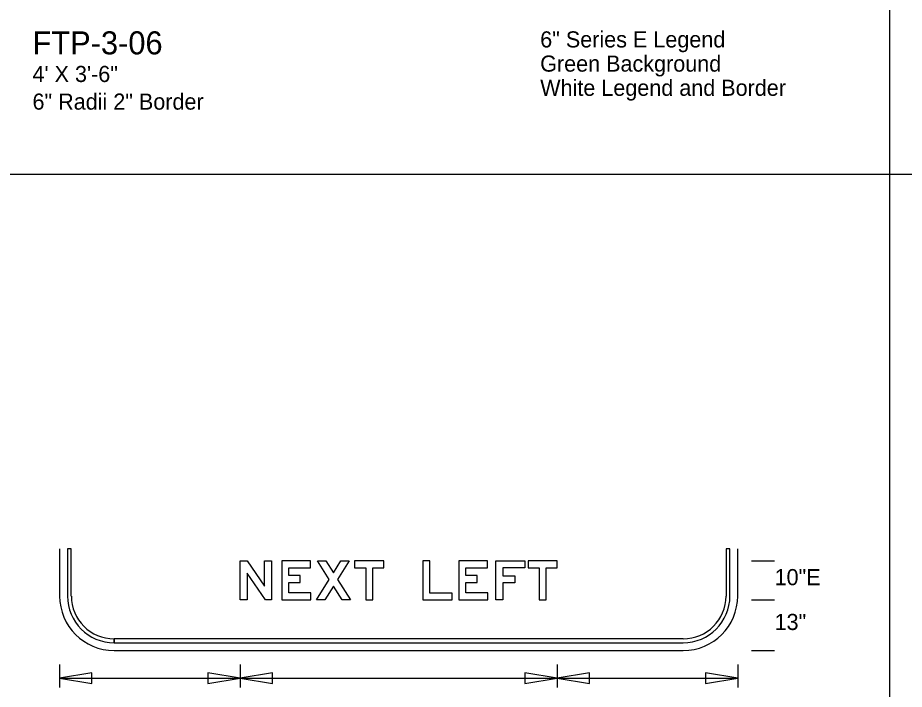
# Model space of a CAD drawing. Extents: x 0 to 770, y 0 to 495.
# Drawn here: x 388.5 to 580.9, y 218.2 to 364 of the extents above; entities that cross this region are included whole.
import ezdxf

# ---------------------------------------------------------------- set-up
doc = ezdxf.new("R2010")
doc.units = 0
for name, color, linetype in [('Dimension', 7, 'Continuous'), ('GSBWFill', 7, 'Continuous'), ('GSColorFill', 7, 'Continuous'), ('GSDims', 7, 'Continuous'), ('GSOutline', 7, 'Continuous'), ('SheetLines_dp', 7, 'Continuous'), ('TextStructures', 7, 'Continuous')]:
    doc.layers.add(name, color=color, linetype=linetype)

msp = doc.modelspace()

# ---------------------------------------------------------------- linework, layer by layer
at = {"layer": 'Dimension'}
for points in [[(397.61, 220.64), (404.63, 219.46), (404.63, 221.83)], [(436.78, 220.64), (429.76, 221.83), (429.76, 219.46)], [(436.78, 220.64), (443.79, 219.46), (443.79, 221.83)], [(505.63, 220.64), (498.61, 221.83), (498.61, 219.46)], [(505.63, 220.64), (512.65, 219.46), (512.65, 221.83)], [(544.79, 220.64), (537.78, 221.83), (537.78, 219.46)]]:
    msp.add_lwpolyline(points, close=True, dxfattribs=at)
at = {"layer": 'GSBWFill'}
for p, q in [((397.61, 248.73), (397.61, 238.48)), ((399.31, 248.73), (399.31, 238.48)), ((400.15, 238.48), (400.15, 248.73)), ((542.26, 248.73), (542.26, 238.48)), ((543.1, 238.48), (543.1, 248.73)), ((544.79, 238.48), (544.79, 248.73)), ((409.46, 228.33), (409.46, 229.18)), ((532.95, 229.18), (409.47, 229.18)), ((409.47, 229.18), (409.47, 228.33)), ((409.47, 228.33), (532.95, 228.33)), ((409.46, 226.64), (532.95, 226.64))]:
    msp.add_line(p, q, dxfattribs=at)
for points in [[(400.15, 248.73), (399.31, 248.73)], [(543.1, 248.73), (542.26, 248.73)]]:
    msp.add_lwpolyline(points, dxfattribs=at)
for points in [[(443.63, 246.09), (443.63, 237.64), (442.32, 237.64), (438.3, 243.43), (438.3, 237.64), (436.78, 237.64), (436.78, 246.09), (438.31, 246.09), (442.11, 240.61), (442.11, 246.09)], [(452.17, 239.16), (447.35, 239.16), (447.35, 241.43), (449.85, 241.43), (449.85, 242.96), (447.35, 242.96), (447.35, 244.57), (452.05, 244.57), (452.05, 246.09), (445.83, 246.09), (445.83, 237.64), (452.17, 237.64)], [(458.92, 237.64), (457.04, 240.63), (455.15, 237.64), (453.36, 237.64), (456.14, 242.07), (453.61, 246.09), (455.41, 246.09), (457.04, 243.5), (458.66, 246.09), (460.46, 246.09), (457.93, 242.07), (460.72, 237.64)], [(461.65, 244.57), (464.06, 244.57), (464.06, 237.64), (465.58, 237.64), (465.58, 244.57), (467.99, 244.57), (467.99, 246.09), (461.65, 246.09)], [(482.79, 237.64), (482.79, 239.12), (477.97, 239.12), (477.97, 246.09), (476.45, 246.09), (476.45, 237.64)], [(490.57, 239.16), (485.75, 239.16), (485.75, 241.43), (488.25, 241.43), (488.25, 242.96), (485.75, 242.96), (485.75, 244.57), (490.45, 244.57), (490.45, 246.09), (484.23, 246.09), (484.23, 237.64), (490.57, 237.64)], [(493.79, 241.36), (493.79, 237.64), (492.27, 237.64), (492.27, 246.09), (498.61, 246.09), (498.61, 244.57), (493.79, 244.57), (493.79, 242.88), (496.45, 242.88), (496.45, 241.36)], [(499.29, 244.57), (501.7, 244.57), (501.7, 237.64), (503.22, 237.64), (503.22, 244.57), (505.63, 244.57), (505.63, 246.09), (499.29, 246.09)]]:
    msp.add_lwpolyline(points, close=True, dxfattribs=at)
for centre, radius, start, end in [((409.46, 238.48), 11.84, 180, 270), ((409.46, 238.48), 10.15, 180, 270), ((409.46, 238.48), 9.3, 180, 270), ((532.95, 238.48), 9.3, 270, 0), ((532.95, 238.48), 10.15, 270, 0), ((532.95, 238.48), 11.84, 270, 0)]:
    msp.add_arc(centre, radius, start, end, dxfattribs=at)
at = {"layer": 'GSColorFill'}
for points in [[(443.63, 246.09), (443.63, 237.64), (442.32, 237.64), (438.3, 243.43), (438.3, 237.64), (436.78, 237.64), (436.78, 246.09), (438.31, 246.09), (442.11, 240.61), (442.11, 246.09)], [(452.17, 239.16), (447.35, 239.16), (447.35, 241.43), (449.85, 241.43), (449.85, 242.96), (447.35, 242.96), (447.35, 244.57), (452.05, 244.57), (452.05, 246.09), (445.83, 246.09), (445.83, 237.64), (452.17, 237.64)], [(458.92, 237.64), (457.04, 240.63), (455.15, 237.64), (453.36, 237.64), (456.14, 242.07), (453.61, 246.09), (455.41, 246.09), (457.04, 243.5), (458.66, 246.09), (460.46, 246.09), (457.93, 242.07), (460.72, 237.64)], [(461.65, 244.57), (464.06, 244.57), (464.06, 237.64), (465.58, 237.64), (465.58, 244.57), (467.99, 244.57), (467.99, 246.09), (461.65, 246.09)], [(482.79, 237.64), (482.79, 239.12), (477.97, 239.12), (477.97, 246.09), (476.45, 246.09), (476.45, 237.64)], [(490.57, 239.16), (485.75, 239.16), (485.75, 241.43), (488.25, 241.43), (488.25, 242.96), (485.75, 242.96), (485.75, 244.57), (490.45, 244.57), (490.45, 246.09), (484.23, 246.09), (484.23, 237.64), (490.57, 237.64)], [(493.79, 241.36), (493.79, 237.64), (492.27, 237.64), (492.27, 246.09), (498.61, 246.09), (498.61, 244.57), (493.79, 244.57), (493.79, 242.88), (496.45, 242.88), (496.45, 241.36)], [(499.29, 244.57), (501.7, 244.57), (501.7, 237.64), (503.22, 237.64), (503.22, 244.57), (505.63, 244.57), (505.63, 246.09), (499.29, 246.09)]]:
    msp.add_lwpolyline(points, close=True, dxfattribs=at)
at = {"layer": 'GSDims'}
for p, q in [((547.79, 246.09), (552.79, 246.09)), ((547.79, 246.09), (552.79, 246.09)), ((547.79, 237.64), (552.79, 237.64)), ((547.79, 237.64), (552.79, 237.64)), ((547.79, 226.64), (552.79, 226.64)), ((397.61, 223.64), (397.61, 218.65)), ((436.78, 223.64), (436.78, 218.65)), ((436.78, 223.64), (436.78, 218.65)), ((505.63, 223.64), (505.63, 218.65)), ((505.63, 223.64), (505.63, 218.65)), ((544.79, 223.64), (544.79, 218.65)), ((397.61, 220.64), (436.78, 220.64)), ((436.78, 220.64), (505.63, 220.64)), ((505.63, 220.64), (544.79, 220.64))]:
    msp.add_line(p, q, dxfattribs=at)
at = {"layer": 'GSOutline'}
for points in [[(443.63, 246.09), (443.63, 237.64), (442.32, 237.64), (438.3, 243.43), (438.3, 237.64), (436.78, 237.64), (436.78, 246.09), (438.31, 246.09), (442.11, 240.61), (442.11, 246.09)], [(452.17, 239.16), (447.35, 239.16), (447.35, 241.43), (449.85, 241.43), (449.85, 242.96), (447.35, 242.96), (447.35, 244.57), (452.05, 244.57), (452.05, 246.09), (445.83, 246.09), (445.83, 237.64), (452.17, 237.64)], [(458.92, 237.64), (457.04, 240.63), (455.15, 237.64), (453.36, 237.64), (456.14, 242.07), (453.61, 246.09), (455.41, 246.09), (457.04, 243.5), (458.66, 246.09), (460.46, 246.09), (457.93, 242.07), (460.72, 237.64)], [(461.65, 244.57), (464.06, 244.57), (464.06, 237.64), (465.58, 237.64), (465.58, 244.57), (467.99, 244.57), (467.99, 246.09), (461.65, 246.09)], [(482.79, 237.64), (482.79, 239.12), (477.97, 239.12), (477.97, 246.09), (476.45, 246.09), (476.45, 237.64)], [(490.57, 239.16), (485.75, 239.16), (485.75, 241.43), (488.25, 241.43), (488.25, 242.96), (485.75, 242.96), (485.75, 244.57), (490.45, 244.57), (490.45, 246.09), (484.23, 246.09), (484.23, 237.64), (490.57, 237.64)], [(493.79, 241.36), (493.79, 237.64), (492.27, 237.64), (492.27, 246.09), (498.61, 246.09), (498.61, 244.57), (493.79, 244.57), (493.79, 242.88), (496.45, 242.88), (496.45, 241.36)], [(499.29, 244.57), (501.7, 244.57), (501.7, 237.64), (503.22, 237.64), (503.22, 244.57), (505.63, 244.57), (505.63, 246.09), (499.29, 246.09)]]:
    msp.add_lwpolyline(points, close=True, dxfattribs=at)
at = {"layer": 'SheetLines_dp'}
for p, q in [((577.8, 0), (577.8, 495)), ((770, 330), (0, 330))]:
    msp.add_line(p, q, dxfattribs=at)

# ---------------------------------------------------------------- texts
at = {"layer": 'TextStructures'}
for s, height, p in [('FTP-3-06', 5, (391.73, 356.06)), ('6" Series E Legend', 3.5, (501.92, 357.56)), ('Green Background', 3.5, (501.92, 352.31)), ('4\' X 3\'-6"', 3.5, (391.73, 350.06)), ('White Legend and Border', 3.5, (501.92, 347.06)), ('6" Radii 2" Border', 3.5, (391.73, 344.06)), ('10"E', 3.5, (552.79, 240.83)), ('13"', 3.5, (552.79, 231.1))]:
    msp.add_text(s, height=height, dxfattribs=at).set_placement(p)

doc.saveas('drawing.dxf')
